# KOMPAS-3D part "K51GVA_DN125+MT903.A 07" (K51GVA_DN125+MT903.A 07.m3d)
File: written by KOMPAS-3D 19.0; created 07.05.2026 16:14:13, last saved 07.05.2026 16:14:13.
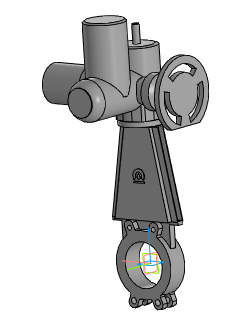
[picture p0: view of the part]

Document properties: Автор: Энергия; Полное имя файла: ..\K51GVA_DN50-DN1000+MT903.A\K51GVA_DN125+MT903.A 07.a3d

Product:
- Part/product: K51GVA_DN125+MT903.A 07
    Масса: 78.7582

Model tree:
1. Операция без истории:1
